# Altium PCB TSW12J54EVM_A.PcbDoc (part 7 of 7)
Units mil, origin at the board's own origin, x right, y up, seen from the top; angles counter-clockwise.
Board outline 6301 x 2680 mil, 10 copper layers (Top Layer - L1, Gnd-Plane - L2, Signals - L3, Gnd-Plane - L4, Pwr Plane - L5, Signals - L6, Gnd-Plane - L7, Signals - L8, Gnd-Plane - L9, Bottom Layer - L10), stack 57.8 mil thick; 650 components, 374 nets, 2074 pads, 1402 vias.
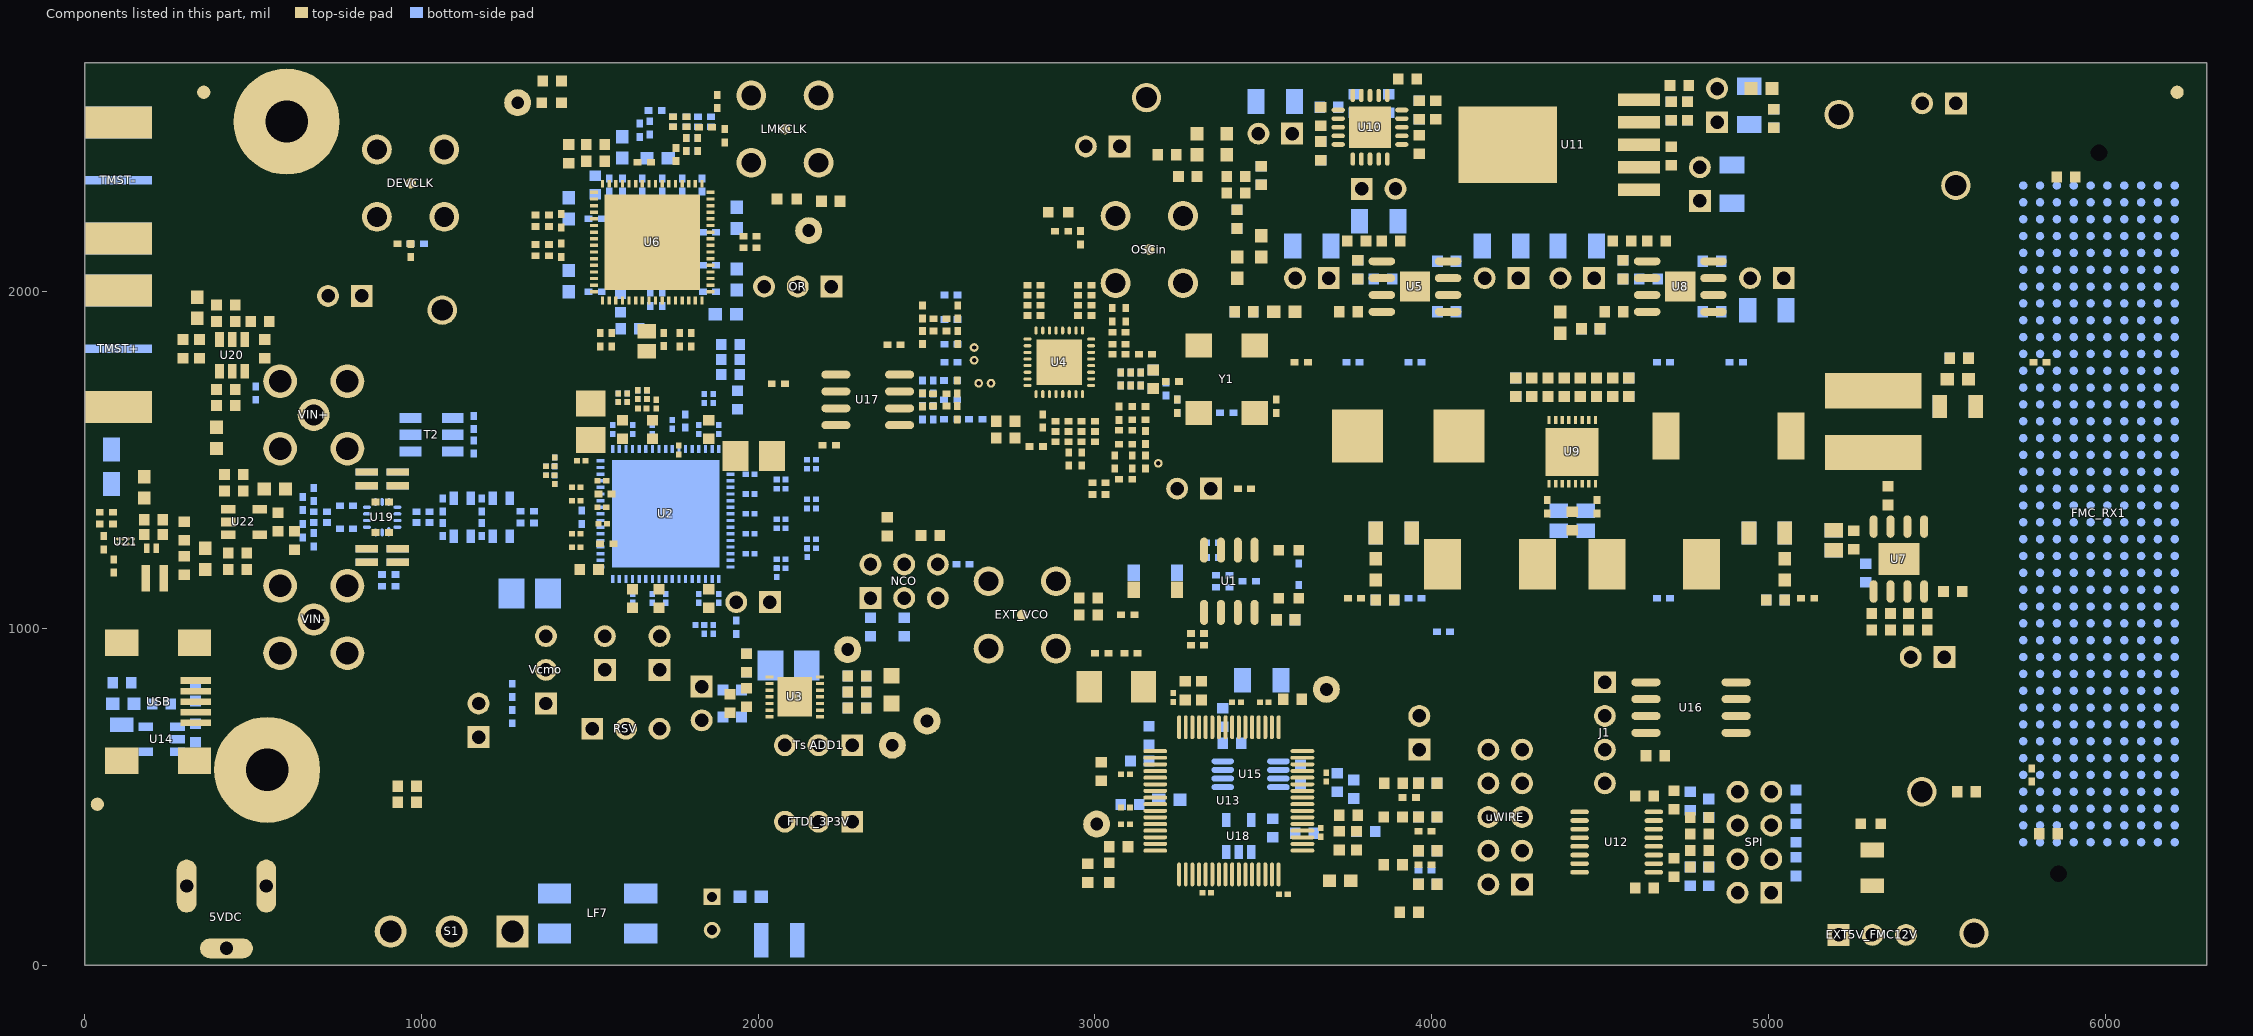
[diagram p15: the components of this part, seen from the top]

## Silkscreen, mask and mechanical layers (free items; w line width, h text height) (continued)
M10 Fab Notes:
  drawing of 207 lines, arcs and shapes, not listed
  text "DESIGN INFORMATION" at 12381.02,6810 h60
  text "(REFER ALSO ARRAY/PANEL PROFILING INFORMATION)" at 12019.46,6648.29 h60
  text "BOARD SIZE" at 11333.46,6644 h60
  text "X" at 12301.46,6516.18 h60
  text "Number of Layers :" at 11736.46,6319 h60
  text "10" at 12831.27,6309 h60
  text "MIN. TRACK WIDTH:" at 11736.46,6180 h60
  text "4" at 12832.7,6180 h60
  text "MIL" at 12987.46,6180 h60
  text "MIN. CLEARANCE:" at 11736.46,6048 h60
  text "4" at 12832.7,6048 h60
  text "MIL" at 12987.46,6048 h60
  text "MIN. VIA PAD SIZE:" at 11736.46,5916 h60
  text "18" at 12802.71,5916 h60
  text "MIL" at 12987.46,5916 h60
  text "0.05mm (2MIL)" at 12431.46,5774.29 h60
  text "MINIMUM ANNULAR RING" at 11407.23,5770 h60
  text "EXTERNAL" at 13139.46,5770 h60
  text "PER" at 11607.23,5652 h60
  text "IPC-D-275 CLASS 2 LEVEL C" at 11827.23,5652 h60
  text "MIL, HOLES" at 13315.46,5539.71 h60
  text "+/-" at 12923,5539 h60
  text "+/-" at 13777,5539 h60
  text "REGISTRATION TOLERANCES:" at 11407.23,5534 h60
  text "METAL" at 12607,5534 h60
  text "5" at 13183.2,5534 h60
  text "3" at 14016.2,5534 h60
  text "MIL" at 14132.46,5534 h60
  text "MATERIAL:" at 11332.46,5324.54 h60
  text "FR-4 High Tg" at 12318.9,5184.21 h60
  text "FR-4" at 11793.46,5175.64 h60
  text "X" at 13054.46,5176 h60
  text "OTHER SEE LAYER STACK UP" at 13241.46,5175.64 h50
  text "62 MIL (1.6mm) +/-10%" at 12073.56,5012.92 h60
  text "THICKNESS:" at 11407.23,5008.64 h60
  text "X" at 11945.4,5008.64 h60
  text "OTHER" at 13358.46,5008.64 h60
  text "TOLERANCE:" at 11407.23,4850.64 h60
  text "X" at 12246.53,4850.64 h60
  text "ANSI IPC-6012 TYPE 3 CLASS 2" at 12433.48,4850.64 h60
  text "OTHER +/-" at 12433.46,4694.64 h60
  text "BOW & TWIST:" at 11407.23,4537.64 h60
  text "X" at 12246.53,4537.64 h60
  text "ANSI IPC-6012 TYPE 3 CLASS 2" at 12433.48,4537.64 h60
  text "OTHER +/-" at 12433.46,4379.13 h60
  text "SEE 001svengprerelstackup18.pdf FOR CORRECT IMPEDANCE INFORMATION" at 5000,4275 h60
  text "COPPER THICKNESS (FINISHED):" at 11332.46,4243.64 h60
  text "Single ended tracks 50 ohms Top & Bottom Layers equal 8.0mil width." at 5000,4125 h60
  text "0.7MIL (0.5oz)" at 12212.46,4090.92 h60
  text "1.4MIL (1oz)" at 12979.46,4090.92 h60
  text "2.8MIL (2oz)" at 13706.46,4090.92 h60
  text "OUTER:" at 11689.46,4086.64 h60
  text "X" at 12084,4086 h60
  text "Differential tracks 100 ohms Top & Bottom Layers equal 8.0mil width & 8.0mil spacing." at 5000,3975 h60
  text "0.7MIL (0.5oz)" at 12212.46,3933.92 h60
  text "2.8MIL (2oz)" at 12979.46,3933.92 h60
  text "N/A" at 13706,3934.29 h60
  text "INNER SIGNAL:" at 11400.38,3929.64 h60
  text "X" at 12085.42,3929.64 h60
  text "X" at 12852.42,3929.64 h60
  text "Differential tracks 100 ohms Inner Layers equal 4.0mil width & 4.0mil spacing." at 5000,3825 h60
  text "DRILLING:" at 11332.46,3790.64 h60
  text "Back Drill high speed lines 8.01 mil vias from Layer 1 to Layer 7, leaving the via connecting layer 8 to layer 10." at 5000,3675 h60
  text "REFERENCE:" at 11407.23,3673.64 h60
  text "X" at 12055.46,3673.64 h60
  text "AS SHOWN" at 12242.46,3673.64 h60
  text "X" at 12956.46,3673.64 h60
  text "NC_DRILL FILES" at 13093.46,3673.64 h60
  text "All Through Vias, 7.874mil, 8mil, 8.01mil, 10mil and 12.992mil, to be Plugged With Non-Conductive Epoxy Material. Plugged Vias to be Plated After" at 5000,3525 h60
  text "PTH MIN COPPER THICKNESS:" at 11407.23,3515.64 h60
  text "X" at 12757.46,3515.64 h60
  text "1MIL" at 12894.46,3515.64 h60
  text "OTHER" at 13391.46,3515.64 h60
  text "Plugging to Present Flat Surface to Device, No Potholes." at 5000,3375 h60
  text "BOARD FINISH:" at 11332.46,3356.64 h60
  text "SILKSCREEN:" at 11487.68,3238.64 h60
  text "X" at 12436.46,3238.64 h60
  text "TOP" at 12562.46,3238.64 h60
  text "X" at 12946.46,3238.64 h60
  text "BOTTOM" at 13073.46,3238.64 h60
  text "SILKSCREEN COLOR:" at 11487.68,3071.64 h60
  text "X" at 12435.42,3071.64 h60
  text "WHITE" at 12562.46,3071.64 h60
  text "OTHER" at 13073.46,3071.64 h60
  text "SOLDER RESIST COLOR:" at 11487.68,2901.64 h60
  text "X" at 12055.42,2742.44 h60
  text "GREEN" at 12182.46,2742.44 h60
  text "BLUE" at 12773.46,2742.44 h60
  text "OTHER" at 13311.46,2742.44 h60
  text "IMMERSION GOLD (ENIG)" at 12393.46,2553.92 h60
  text "SURFACE FINISH:" at 11332.46,2549.64 h60
  text "X" at 12206.51,2549.64 h60
  text "IMM. TIN/SILVER OR EQUIV" at 11662,2392.64 h60
  text "OTHER" at 13093.46,2392.64 h60
  text "ARRAY/PANEL:" at 11332.46,2213.64 h60
  text "CUT AND TRIM PER MECH LAYER 1" at 12393.46,2209.35 h60
  text "N.C. ROUTE" at 12393.46,2057.64 h60
  text "X" at 13072.46,2057.64 h60
  text "V. SCORE" at 13259.46,2057.64 h60
  text "CERTIFICATION:" at 11332.46,1920.64 h60
  text "MATERIALS AND WORKMANSHIP FOR ALL PCBS" at 12057.46,1920.64 h60
  text "TO MEET OR EXCEED THE REQUIREMENTS OF:" at 12057.46,1822.64 h60
  text "X" at 11683.96,1686.13 h60
  text "ANSI IPC-A-600F CLASS ->" at 11822.96,1686.13 h60
  text "X" at 13462.02,1686.13 h60
  text "2" at 13580.96,1686.14 h60
  text "1" at 13265.96,1684.64 h60
  text "3" at 13934.96,1684.64 h60
  text "X" at 11686.02,1526.64 h60
  text "UL 94V-0" at 11822.96,1526.64 h60
  text "X" at 12498.02,1526.64 h60
  text "RoHS" at 12634.96,1526.64 h60
  text "OTHER" at 13279.36,1526.64 h60
  text "PER ORDER" at 13676.42,1526.64 h60
  text "ADDITIONAL REQUIREMENTS:" at 11332.46,1385.64 h60
  text "MICROSECTION:" at 11407.23,1270.64 h60
  text "YES" at 12312.96,1270.64 h60
  text "REQUIRED" at 13174.46,1114.49 h60
  text "BARE BOARD ELEC. TEST:" at 11407.23,1111.64 h60
  text "NONE" at 12712.96,1111.64 h60
  text "X" at 13047.46,1111.64 h60
  text "PER ORDER" at 13766.46,1111.64 h60
  text "MANUFACTURER'S ID/LOGO:" at 11407.23,954.64 h60
  text "RAIL" at 12872.96,950.35 h60
  text "X" at 13247.46,950.35 h60
  text "METAL" at 13364.77,950.35 h60
  text "SILK" at 13876.46,950.35 h60
  text ".Layer_Name" at 577,-858.49 h60
M11 Gerber Information:
  lines w10: -292,-930.17 6308,-930.17 ; -292,-726.83 6310,-726.83 ; -292,-523.5 -292,-1133.5 3713,-1133.5 6310,-1133.5 6310,-523.5 -291.5,-523.5 -291.5,-1133.5 1284,-1133.5 ; 2173,-1133.5 2173,-523.5 ; 3440,-726.83 3440,-523.5 ; 4280,-726.83 4280,-523.5 ; 4902,-1140 4902,-937.17
  text "ALL ARTWORK VIEWED FROM TOP SIDE" at -228.5,-655.67 h60
  text "BOARD #:" at 2248,-655.67 h60
  text ".PRJ_Number" at 2793.5,-655.67 h60
  text "REV:" at 3638,-655.67 h60
  text ".PCB_Rev" at 3929.5,-655.67 h60
  text "SVN REV:" at 4476,-655.67 h60
  text ".VersionControl_RevNumber" at 4982,-655.67 h60
  text "LAYER NAME =" at -228.5,-858.49 h60
  text "PLOT NAME =" at -228.5,-1064.34 h60
  text ".plot_File_Name" at 577,-1064.34 h60
  text "GENERATED    :" at 2250,-1064.34 h60
  text ".Print_Date" at 3119.5,-1064.34 h60
  text ".Print_Time" at 3848.5,-1064.34 h60
  text "TEXAS INSTRUMENTS" at 5113,-1064.34 h60
M12 Stackup:
  lines w11: 4912,4388 4125,6075 4912,7762
  lines w12: 5018.02,7259.85 11193.98,7259.85 ; 5018.02,7472.75 11193.98,7472.75 ; 4955,4449 ccw(c5024,4449) 5024,4380 11188,4380 ccw(c11188,4449) 11257,4449 11257,7692 ccw(c11188,7692) 11188,7761 5024,7761 ccw(c5024,7692) 4955,7692 4955,4449
  text "Layer Stack Up Detail for: TSW12J54EVM_A.PcbDoc" at 5018.02,7534.88 h110
  text "Layer" at 5018.02,7393.25 h49
  text "Gerber" at 6358.46,7393.25 h49
  text "Copper" at 7016.09,7393.25 h49
  text "Dielectric" at 7753.73,7393.25 h49
  text "Dielectric" at 8525.66,7393.25 h49
  text "Dielectric" at 9509.72,7393.25 h49
  text "Dielectric" at 10281.65,7393.25 h49
  text "Name" at 5018.02,7295.25 h49
  text "Document" at 6358.46,7295.25 h49
  text "Thickness" at 7016.09,7295.25 h49
  text "Height" at 7753.73,7295.25 h49
  text "Material" at 8525.66,7295.25 h49
  text "Constant" at 9509.72,7295.25 h49
  text "Type" at 10281.65,7295.25 h49
  text "Top Solder Mask" at 5018.02,7142.44 h69
  text "(.GTS)" at 6358.46,7142.44 h69
  text "0.4mil" at 7753.73,7142.44 h69
  text "Solder Resist" at 8525.66,7142.44 h69
  text "3.50" at 9509.72,7142.44 h69
  text "Top Layer - L1" at 5018.02,6919.62 h69
  text "(.GTL)" at 6358.46,6919.62 h69
  text "0.6mil" at 7016.09,6919.62 h69
  text "4mil" at 7753.73,6808.21 h69
  text "Rogers RO4350" at 8525.66,6808.21 h69
  text "3.66" at 9509.72,6808.21 h69
  text "Core" at 10281.65,6808.21 h69
  text "Gnd-Plane - L2" at 5018.02,6696.8 h69
  text "(.GP1)" at 6358.46,6696.8 h69
  text "1.2mil" at 7016.09,6696.8 h69
  text "6.7mil" at 7753.73,6585.39 h69
  text "Isola 370HR" at 8525.66,6585.39 h69
  text "4.11" at 9509.72,6585.39 h69
  text "PrePreg" at 10281.65,6585.39 h69
  text "Signals - L3" at 5018.02,6473.98 h69
  text "(.G1)" at 6358.46,6473.98 h69
  text "0.6mil" at 7016.09,6473.98 h69
  text "6mil" at 7753.73,6362.57 h69
  text "Isola 370HR" at 8525.66,6362.57 h69
  text "4.11" at 9509.72,6362.57 h69
  text "Core" at 10281.65,6362.57 h69
  text "Gnd-Plane - L4" at 5018.02,6251.16 h69
  text "(.GP2)" at 6358.46,6251.16 h69
  text "1.2mil" at 7016.09,6251.16 h69
  text "4.1mil" at 7753.73,6139.75 h69
  text "Isola 370HR" at 8525.66,6139.75 h69
  text "4.11" at 9509.72,6139.75 h69
  text "PrePreg" at 10281.65,6139.75 h69
  text "SEE 001svengprerelstackup18.pdf FOR CORRECT STACKUP INFORMATION" at -46,6041 h66
  text "Pwr Plane - L5" at 5018.02,6028.34 h69
  text "(.GP3)" at 6358.46,6028.34 h69
  text "1.2mil" at 7016.09,6028.34 h69
  text "6mil" at 7753.73,5916.93 h69
  text "Isola 370HR" at 8525.66,5916.93 h69
  text "4.11" at 9509.72,5916.93 h69
  text "Core" at 10281.65,5916.93 h69
  text "Signals - L6" at 5018.02,5805.51 h69
  text "(.G2)" at 6358.46,5805.51 h69
  text "0.6mil" at 7016.09,5805.51 h69
  text "6.7mil" at 7753.73,5694.1 h69
  text "Isola 370HR" at 8525.66,5694.1 h69
  text "4.11" at 9509.72,5694.1 h69
  text "PrePreg" at 10281.65,5694.1 h69
  text "Gnd-Plane - L7" at 5018.02,5582.69 h69
  text "(.GP4)" at 6358.46,5582.69 h69
  text "1.2mil" at 7016.09,5582.69 h69
  text "4mil" at 7753.73,5471.28 h69
  text "Rogers RO4350" at 8525.66,5471.28 h69
  text "3.66" at 9509.72,5471.28 h69
  text "Core" at 10281.65,5471.28 h69
  text "Signals - L8" at 5018.02,5359.87 h69
  text "(.G3)" at 6358.46,5359.87 h69
  text "0.6mil" at 7016.09,5359.87 h69
  text "7.3mil" at 7753.73,5248.46 h69
  text "Rogers RO4350" at 8525.66,5248.46 h69
  text "3.66" at 9509.72,5248.46 h69
  text "PrePreg" at 10281.65,5248.46 h69
  text "Gnd-Plane - L9" at 5018.02,5137.05 h69
  text "(.GP5)" at 6358.46,5137.05 h69
  text "1.2mil" at 7016.09,5137.05 h69
  text "4mil" at 7753.73,5025.64 h69
  text "Rogers RO4350" at 8525.66,5025.64 h69
  text "3.66" at 9509.72,5025.64 h69
  text "Core" at 10281.65,5025.64 h69
  text "Bottom Layer - L10" at 5018.02,4914.23 h69
  text "(.GBL)" at 6358.46,4914.23 h69
  text "0.6mil" at 7016.09,4914.23 h69
  text "Bottom Solder Mask" at 5018.02,4691.41 h69
  text "(.GBS)" at 6358.46,4691.41 h69
  text "0.4mil" at 7753.73,4691.41 h69
  text "Solder Resist" at 8525.66,4691.41 h69
  text "3.50" at 9509.72,4691.41 h69
  text ".Layer_Name" at 577,-858.49 h60
M13 Component Bodies Top:
  text ".Layer_Name" at 577,-858.49 h60
M14 Component Bodies Bottom:
  text ".Layer_Name" at 577,-858.49 h60
M15 Courtyards Top:
  text ".Layer_Name" at 577,-858.49 h60
M16 Courtyards Bottom:
  text ".Layer_Name" at 577,-858.49 h60
Drill Drawing:
  text ".legend" at 6576.5,725.5 h60
  text "Drill Table" at 6601.5,540.5 h60
  text ".Layer_Name" at 577,-858.49 h60

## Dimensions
0,0 to 0,2680 on M2 Board Dimensions
0,0 to 6301,0 on M2 Board Dimensions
